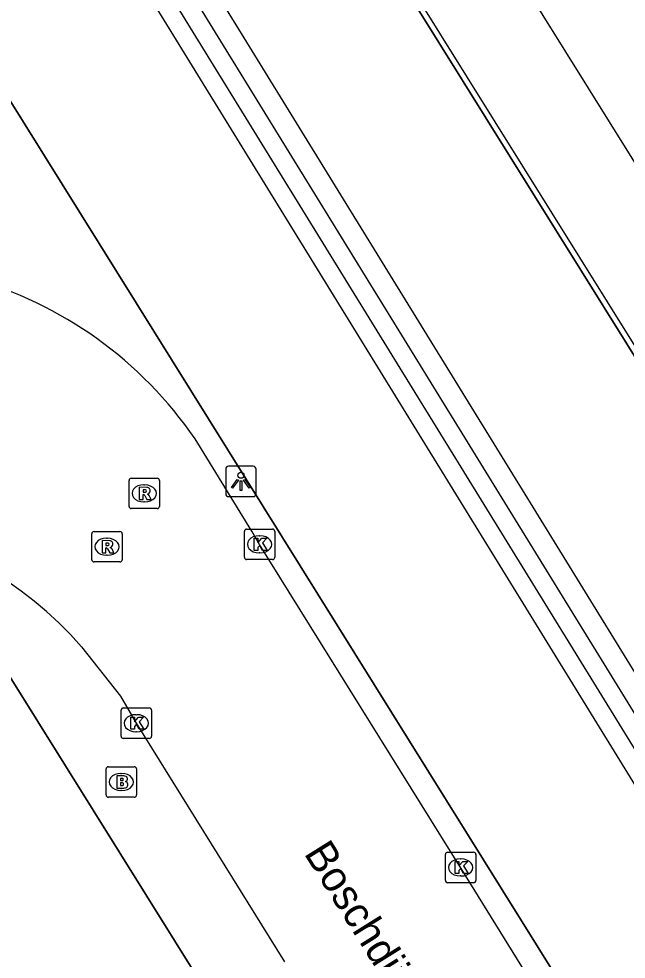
# Model space of a CAD drawing. Extents: x 158838 to 160074, y 386376 to 387776.
# Drawn here: x 159182.34 to 159202.27, y 386799.5 to 386830.39 of the extents above; entities that cross this region are included whole.
import ezdxf

# ---------------------------------------------------------------- set-up
doc = ezdxf.new("R2010")
doc.units = 0
for name, color, linetype in [('IMGEO_Berm_groen', 7, 'Continuous'), ('IMGEO_Brandkraan', 7, 'Continuous'), ('IMGEO_Groenvoorziening', 7, 'Continuous'), ('IMGEO_Hek', 7, 'Continuous'), ('IMGEO_Kolk', 7, 'Continuous'), ('IMGEO_Lichtpunt', 7, 'Continuous'), ('IMGEO_Openbare_ruimte_label', 7, 'Continuous'), ('IMGEO_Rijbaan_lokaal_open', 7, 'Continuous'), ('IMGEO_Rioolput', 7, 'Continuous'), ('IMGEO_Voetpad_open', 7, 'Continuous')]:
    doc.layers.add(name, color=color, linetype=linetype)

msp = doc.modelspace()

# ---------------------------------------------------------------- linework, layer by layer
at = {"layer": 'IMGEO_Berm_groen'}
msp.add_lwpolyline([(159221.856, 386775.703), (159220.103, 386774.566), (159215.005, 386774.81), (159181.964, 386827.844)], dxfattribs=at)
at = {"layer": 'IMGEO_Brandkraan'}
for p, q in [((159185.199, 386804.899), (159185.199, 386805.751)), ((159185.274, 386805.825), (159186.126, 386805.825)), ((159185.687, 386805.605), (159185.712, 386805.605)), ((159186.2, 386805.751), (159186.2, 386804.899)), ((159185.71, 386805.045), (159185.685, 386805.045)), ((159186.126, 386804.825), (159185.274, 386804.825))]:
    msp.add_line(p, q, dxfattribs=at)
for points in [[(159185.199, 386804.899), (159185.199, 386805.751)], [(159185.274, 386805.825), (159186.126, 386805.825)], [(159186.2, 386805.751), (159186.2, 386804.899)], [(159185.547, 386805.525), (159185.547, 386805.125), (159185.76, 386805.125)], [(159185.778, 386805.525), (159185.547, 386805.525)], [(159185.726, 386805.444), (159185.672, 386805.444), (159185.672, 386805.368)], [(159185.672, 386805.368), (159185.725, 386805.368)], [(159185.734, 386805.292), (159185.672, 386805.292), (159185.672, 386805.211)], [(159185.672, 386805.211), (159185.734, 386805.211)], [(159186.126, 386804.825), (159185.274, 386804.825)]]:
    msp.add_lwpolyline(points, dxfattribs=at)
for centre, radius, start, end in [((159185.276, 386805.749), 0.0765, 91.552, 178.448), ((159185.276, 386805.749), 0.0765, 91.552, 178.448), ((159186.124, 386805.749), 0.0765, 1.552, 88.448), ((159186.124, 386805.749), 0.0765, 1.552, 88.448), ((159185.727, 386805.406), 0.0379, 267.8285, 90.9355), ((159185.735, 386805.251), 0.0404, 269.8759, 90.5077), ((159185.782, 386805.38), 0.145, 59.4692, 91.5367), ((159185.807, 386805.427), 0.0922, 285.5137, 58.1501), ((159185.812, 386805.235), 0.105, 301.3115, 78.989), ((159185.766, 386805.376), 0.251, 268.6676, 293.5347), ((159185.276, 386804.901), 0.0765, 181.552, 268.448), ((159185.276, 386804.901), 0.0765, 181.552, 268.448), ((159186.124, 386804.901), 0.0765, 271.552, 358.448), ((159186.124, 386804.901), 0.0765, 271.552, 358.448)]:
    msp.add_arc(centre, radius, start, end, dxfattribs=at)
for centre, major_axis, ratio, start_param, end_param in [((159185.686, 386805.325), (-0.387, 0.002), 0.722429, 4.712389, 7.853982), ((159185.711, 386805.325), (-0.39, 0.002), 0.717154, 1.570796, 4.712389)]:
    msp.add_ellipse(centre, major_axis=major_axis, ratio=ratio, start_param=start_param, end_param=end_param, dxfattribs=at)
at = {"layer": 'IMGEO_Groenvoorziening'}
for points in [[(159182.122, 386834.323), (159182.77, 386834.218), (159183.406, 386834.055), (159184.024, 386833.836), (159184.621, 386833.563), (159185.191, 386833.237), (159185.729, 386832.862), (159186.232, 386832.44), (159186.695, 386831.975), (159187.115, 386831.471), (159218.557, 386780.384), (159219.079, 386780.692), (159188.092, 386831.097), (159187.73, 386831.664), (159187.319, 386832.197), (159186.862, 386832.691), (159186.362, 386833.142), (159185.825, 386833.546), (159185.253, 386833.901), (159185.183, 386833.94)], [(159225.425, 386782.595), (159193.034, 386834.571)], [(159181.955, 386833.72), (159182.549, 386833.637), (159183.133, 386833.501), (159183.703, 386833.314), (159184.253, 386833.077), (159184.781, 386832.791), (159185.28, 386832.459), (159185.748, 386832.084), (159186.181, 386831.669), (159186.575, 386831.217), (159218.054, 386780.026)], [(159188.511, 386831.756), (159188.704, 386831.434), (159219.711, 386781.007), (159219.734, 386780.957), (159219.765, 386780.877), (159219.789, 386780.794), (159219.805, 386780.709), (159219.813, 386780.623), (159219.814, 386780.537), (159219.807, 386780.451), (159219.793, 386780.366), (159219.77, 386780.282), (159219.741, 386780.201), (159219.704, 386780.123), (159219.661, 386780.049), (159219.611, 386779.978), (159219.555, 386779.913), (159219.493, 386779.852), (159219.426, 386779.798), (159219.355, 386779.749), (159219.279, 386779.708), (159219.263, 386779.701)]]:
    msp.add_lwpolyline(points, dxfattribs=at)
at = {"layer": 'IMGEO_Hek'}
for points in [[(159193.034, 386834.571), (159225.425, 386782.595)], [(159181.964, 386827.844), (159215.005, 386774.81), (159220.103, 386774.566), (159221.856, 386775.703)], [(159189.265, 386797.201), (159182.052, 386808.764), (159180.897, 386809.75), (159178.798, 386810.825), (159176.512, 386811.455), (159174.154, 386811.455), (159171.857, 386810.878), (159136.254, 386788.629)]]:
    msp.add_lwpolyline(points, dxfattribs=at)
at = {"layer": 'IMGEO_Kolk'}
for p, q in [((159189.812, 386813.63), (159190.664, 386813.63)), ((159189.737, 386812.704), (159189.737, 386813.556)), ((159190.225, 386813.41), (159190.25, 386813.41)), ((159190.738, 386813.556), (159190.738, 386812.704)), ((159190.248, 386812.85), (159190.223, 386812.85)), ((159190.664, 386812.63), (159189.812, 386812.63)), ((159185.765, 386807.755), (159186.617, 386807.755)), ((159185.69, 386806.829), (159185.69, 386807.681)), ((159186.178, 386807.535), (159186.203, 386807.535)), ((159186.691, 386807.681), (159186.691, 386806.829)), ((159186.201, 386806.975), (159186.176, 386806.975)), ((159186.617, 386806.755), (159185.765, 386806.755)), ((159196.334, 386802.091), (159196.334, 386802.943)), ((159196.409, 386803.017), (159197.261, 386803.017)), ((159196.822, 386802.797), (159196.847, 386802.797)), ((159197.335, 386802.943), (159197.335, 386802.091)), ((159196.845, 386802.237), (159196.82, 386802.237)), ((159197.261, 386802.017), (159196.409, 386802.017))]:
    msp.add_line(p, q, dxfattribs=at)
for points in [[(159189.812, 386813.63), (159190.664, 386813.63)], [(159189.737, 386812.704), (159189.737, 386813.556)], [(159190.058, 386813.33), (159190.181, 386813.33), (159190.181, 386813.179), (159190.311, 386813.33), (159190.475, 386813.33), (159190.329, 386813.179), (159190.482, 386812.93), (159190.33, 386812.93), (159190.245, 386813.094), (159190.181, 386813.027), (159190.181, 386812.93), (159190.058, 386812.93), (159190.058, 386813.33)], [(159190.738, 386813.556), (159190.738, 386812.704)], [(159190.664, 386812.63), (159189.812, 386812.63)], [(159185.765, 386807.755), (159186.617, 386807.755)], [(159185.69, 386806.829), (159185.69, 386807.681)], [(159186.011, 386807.455), (159186.134, 386807.455), (159186.134, 386807.304), (159186.264, 386807.455), (159186.428, 386807.455), (159186.282, 386807.304), (159186.435, 386807.055), (159186.283, 386807.055), (159186.198, 386807.219), (159186.134, 386807.152), (159186.134, 386807.055), (159186.011, 386807.055), (159186.011, 386807.455)], [(159186.691, 386807.681), (159186.691, 386806.829)], [(159186.617, 386806.755), (159185.765, 386806.755)], [(159196.334, 386802.091), (159196.334, 386802.943)], [(159196.409, 386803.017), (159197.261, 386803.017)], [(159197.335, 386802.943), (159197.335, 386802.091)], [(159196.655, 386802.717), (159196.778, 386802.717), (159196.778, 386802.566), (159196.908, 386802.717), (159197.072, 386802.717), (159196.926, 386802.566), (159197.079, 386802.317), (159196.927, 386802.317), (159196.842, 386802.481), (159196.778, 386802.414), (159196.778, 386802.317), (159196.655, 386802.317), (159196.655, 386802.717)], [(159197.261, 386802.017), (159196.409, 386802.017)]]:
    msp.add_lwpolyline(points, dxfattribs=at)
for centre, start, end in [((159189.814, 386813.554), 91.552, 178.448), ((159189.814, 386813.554), 91.552, 178.448), ((159190.662, 386813.554), 1.552, 88.448), ((159190.662, 386813.554), 1.552, 88.448), ((159189.814, 386812.706), 181.552, 268.448), ((159189.814, 386812.706), 181.552, 268.448), ((159190.662, 386812.706), 271.552, 358.448), ((159190.662, 386812.706), 271.552, 358.448), ((159185.767, 386807.679), 91.552, 178.448), ((159185.767, 386807.679), 91.552, 178.448), ((159186.615, 386807.679), 1.552, 88.448), ((159186.615, 386807.679), 1.552, 88.448), ((159185.767, 386806.831), 181.552, 268.448), ((159185.767, 386806.831), 181.552, 268.448), ((159186.615, 386806.831), 271.552, 358.448), ((159186.615, 386806.831), 271.552, 358.448), ((159196.411, 386802.941), 91.552, 178.448), ((159196.411, 386802.941), 91.552, 178.448), ((159197.259, 386802.941), 1.552, 88.448), ((159197.259, 386802.941), 1.552, 88.448), ((159196.411, 386802.093), 181.552, 268.448), ((159196.411, 386802.093), 181.552, 268.448), ((159197.259, 386802.093), 271.552, 358.448), ((159197.259, 386802.093), 271.552, 358.448)]:
    msp.add_arc(centre, 0.0765, start, end, dxfattribs=at)
for centre, major_axis, ratio, start_param, end_param in [((159190.224, 386813.13), (-0.387, 0.002), 0.722429, 4.712389, 7.853982), ((159190.249, 386813.13), (-0.39, 0.002), 0.717154, 1.570796, 4.712389), ((159186.177, 386807.255), (-0.387, 0.002), 0.722429, 4.712389, 7.853982), ((159186.202, 386807.255), (-0.39, 0.002), 0.717154, 1.570796, 4.712389), ((159196.821, 386802.517), (-0.387, 0.002), 0.722429, 4.712389, 7.853982), ((159196.846, 386802.517), (-0.39, 0.002), 0.717154, 1.570796, 4.712389)]:
    msp.add_ellipse(centre, major_axis=major_axis, ratio=ratio, start_param=start_param, end_param=end_param, dxfattribs=at)
at = {"layer": 'IMGEO_Lichtpunt'}
for p, q in [((159189.127, 386815.6), (159189.127, 386814.793)), ((159189.127, 386815.6), (159189.127, 386814.793)), ((159190.029, 386815.695), (159189.221, 386815.695)), ((159190.029, 386815.695), (159189.221, 386815.695)), ((159190.123, 386814.793), (159190.123, 386815.6)), ((159190.123, 386814.793), (159190.123, 386815.6)), ((159189.221, 386814.699), (159190.029, 386814.699)), ((159189.221, 386814.699), (159190.029, 386814.699))]:
    msp.add_line(p, q, dxfattribs=at)
for points in [[(159189.501, 386815.264), (159189.54, 386815.236), (159189.352, 386814.974), (159189.314, 386815.001), (159189.501, 386815.264)], [(159189.603, 386815.216), (159189.65, 386815.216), (159189.65, 386814.894), (159189.603, 386814.894), (159189.603, 386815.216)], [(159189.713, 386815.236), (159189.751, 386815.263), (159189.938, 386815.001), (159189.899, 386814.973), (159189.713, 386815.236)]]:
    msp.add_lwpolyline(points, dxfattribs=at)
msp.add_circle((159189.626, 386815.398), 0.0994, dxfattribs=at)
for centre, start, end in [((159189.221, 386815.6), 90, 180), ((159189.221, 386815.6), 90, 180), ((159190.029, 386815.6), 0, 90), ((159190.029, 386815.6), 0, 90), ((159189.221, 386814.793), 180, 270), ((159189.221, 386814.793), 180, 270), ((159190.029, 386814.793), 270, 0), ((159190.029, 386814.793), 270, 360)]:
    msp.add_arc(centre, 0.0946, start, end, dxfattribs=at)
at = {"layer": 'IMGEO_Rijbaan_lokaal_open'}
for points in [[(159188.529, 386848.144), (159190.768, 386844.567), (159203.199, 386824.618), (159213.548, 386808.108), (159218.217, 386800.643), (159218.869, 386799.586)], [(159215.274, 386772.727), (159214.927, 386773.26), (159203.911, 386791.078), (159196.853, 386802.486), (159190.237, 386813.13), (159189.98, 386813.56), (159188.119, 386816.595)], [(159184.396, 386809.768), (159185.669, 386808.14), (159186.192, 386807.255), (159191.052, 386799.421)]]:
    msp.add_lwpolyline(points, dxfattribs=at)
for centre, radius, start, end in [((159177.185, 386809.118), 13.246, 34.3638, 74.4081), ((159175.151, 386801.696), 12.273, 41.1258, 119.8842)]:
    msp.add_arc(centre, radius, start, end, dxfattribs=at)
at = {"layer": 'IMGEO_Rioolput'}
for p, q in [((159185.952, 386814.378), (159185.952, 386815.23)), ((159186.027, 386815.304), (159186.879, 386815.304)), ((159186.953, 386815.23), (159186.953, 386814.378)), ((159186.44, 386815.084), (159186.465, 386815.084)), ((159186.463, 386814.524), (159186.438, 386814.524)), ((159186.879, 386814.304), (159186.027, 386814.304)), ((159184.729, 386812.626), (159184.729, 386813.478)), ((159184.804, 386813.552), (159185.656, 386813.552)), ((159185.217, 386813.332), (159185.242, 386813.332)), ((159185.73, 386813.478), (159185.73, 386812.626)), ((159185.24, 386812.772), (159185.215, 386812.772)), ((159185.656, 386812.552), (159184.804, 386812.552))]:
    msp.add_line(p, q, dxfattribs=at)
for points in [[(159185.952, 386814.378), (159185.952, 386815.23)], [(159186.027, 386815.304), (159186.879, 386815.304)], [(159186.953, 386815.23), (159186.953, 386814.378)], [(159186.541, 386815.002), (159186.289, 386815.004), (159186.289, 386814.604)], [(159186.467, 386814.923), (159186.413, 386814.923), (159186.413, 386814.842)], [(159186.413, 386814.842), (159186.465, 386814.842)], [(159186.289, 386814.604), (159186.413, 386814.604), (159186.413, 386814.766), (159186.424, 386814.766)], [(159186.471, 386814.737), (159186.542, 386814.604), (159186.682, 386814.604), (159186.617, 386814.73)], [(159186.879, 386814.304), (159186.027, 386814.304)], [(159184.729, 386812.626), (159184.729, 386813.478)], [(159184.804, 386813.552), (159185.656, 386813.552)], [(159185.73, 386813.478), (159185.73, 386812.626)], [(159185.318, 386813.25), (159185.066, 386813.252), (159185.066, 386812.852)], [(159185.066, 386812.852), (159185.19, 386812.852), (159185.19, 386813.014), (159185.201, 386813.014)], [(159185.244, 386813.171), (159185.19, 386813.171), (159185.19, 386813.09)], [(159185.19, 386813.09), (159185.242, 386813.09)], [(159185.248, 386812.985), (159185.319, 386812.852), (159185.459, 386812.852), (159185.394, 386812.978)], [(159185.656, 386812.552), (159184.804, 386812.552)]]:
    msp.add_lwpolyline(points, dxfattribs=at)
for centre, radius, start, end in [((159186.029, 386815.228), 0.0765, 91.552, 178.448), ((159186.029, 386815.228), 0.0765, 91.552, 178.448), ((159186.877, 386815.228), 0.0765, 1.552, 88.448), ((159186.877, 386815.228), 0.0765, 1.552, 88.448), ((159186.449, 386815.031), 0.19, 274.7715, 282.9687), ((159186.473, 386814.827), 0.0964, 77.0061, 93.1865), ((159186.487, 386814.884), 0.0378, 276.6634, 79.6772), ((159186.54, 386814.892), 0.109, 350.3612, 89.416), ((159186.538, 386814.892), 0.112, 277.5842, 350.9817), ((159186.423, 386814.713), 0.0533, 26.0293, 88.6989), ((159186.522, 386814.677), 0.108, 29.5134, 73.7905), ((159186.029, 386814.38), 0.0765, 181.552, 268.448), ((159186.029, 386814.38), 0.0765, 181.552, 268.448), ((159186.877, 386814.38), 0.0765, 271.552, 358.448), ((159186.877, 386814.38), 0.0765, 271.552, 358.448), ((159184.806, 386813.476), 0.0765, 91.552, 178.448), ((159184.806, 386813.476), 0.0765, 91.552, 178.448), ((159185.654, 386813.476), 0.0765, 1.552, 88.448), ((159185.654, 386813.476), 0.0765, 1.552, 88.448), ((159185.2, 386812.961), 0.0533, 26.0293, 88.6989), ((159185.226, 386813.279), 0.19, 274.7715, 282.9687), ((159185.25, 386813.075), 0.0964, 77.0061, 93.1865), ((159185.264, 386813.132), 0.0378, 276.6634, 79.6772), ((159185.317, 386813.14), 0.109, 350.3612, 89.416), ((159185.315, 386813.14), 0.112, 277.5842, 350.9817), ((159185.299, 386812.925), 0.108, 29.5134, 73.7905), ((159184.806, 386812.628), 0.0765, 181.552, 268.448), ((159184.806, 386812.628), 0.0765, 181.552, 268.448), ((159185.654, 386812.628), 0.0765, 271.552, 358.448), ((159185.654, 386812.628), 0.0765, 271.552, 358.448)]:
    msp.add_arc(centre, radius, start, end, dxfattribs=at)
for centre, major_axis, ratio, start_param, end_param in [((159186.439, 386814.804), (-0.387, 0.002), 0.722429, 4.712389, 7.853982), ((159186.464, 386814.804), (-0.39, 0.002), 0.717154, 1.570796, 4.712389), ((159185.216, 386813.052), (-0.387, 0.002), 0.722429, 4.712389, 7.853982), ((159185.241, 386813.052), (-0.39, 0.002), 0.717154, 1.570796, 4.712389)]:
    msp.add_ellipse(centre, major_axis=major_axis, ratio=ratio, start_param=start_param, end_param=end_param, dxfattribs=at)
at = {"layer": 'IMGEO_Voetpad_open'}
for points in [[(159190.588, 386838.84), (159215.479, 386798.902), (159215.834, 386798.34), (159225.683, 386782.752)], [(159182.052, 386808.764), (159189.265, 386797.201)]]:
    msp.add_lwpolyline(points, dxfattribs=at)

# ---------------------------------------------------------------- texts
at = {"layer": 'IMGEO_Openbare_ruimte_label'}
msp.add_text('Boschdijk', height=1, rotation=302.0539, dxfattribs=at).set_placement((159191.676, 386802.98))

doc.saveas('drawing.dxf')
